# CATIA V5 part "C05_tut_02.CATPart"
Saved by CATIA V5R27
Part number: Part1
Bounding box of the stored display mesh (mm): x -20 to 5, y -42.139 to 42.139, z 0 to 101.99
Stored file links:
  E:\_Deepak\2017_Deepak\CATIA\Resources\Tutorial Files\Tutorials\c05_catia_v5_6r2016_tut\C05_tut_02.CATPart
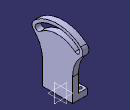
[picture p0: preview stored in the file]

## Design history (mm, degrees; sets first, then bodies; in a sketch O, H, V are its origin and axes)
Body1 (main body)
  Sketch1 on yz-plane, origin (0, 0, 0), H (0, 1, 0), V (0, 0, 1)
    point P1 (-25, 0)
    line L1 (-25, 0) -> (25, 0)
    point P2 (25, 0)
    line L2 (-25, 0) -> (-25, 38.3145)
    point P3 (-25, 38.3145)
    arc A1 centre (0, 42) radius 60 from (38.5673, 87.9627) to (-38.5673, 87.9627) ccw
    point P4 (0, 42)
    axis line L3 (0, 42) -> (-54.0665, 106.434)
    point P5 (-54.0665, 106.434)
    point P6 (54.0665, 106.434)
    point P7 (0, 42)
    construction line L4 (0, 42) -> (54.0665, 106.434)
    point P8 (-38.5673, 87.9627)
    point P9 (38.5673, 87.9627)
    arc A2 centre (-32.1394, 80.3022) radius 10 from (-38.5673, 87.9627) to (-39.2828, 73.3043) ccw
    point P10 (-32.1394, 80.3022)
    arc A3 centre (32.1394, 80.3022) radius 10 from (38.5673, 87.9627) to (39.2828, 73.3043) cw
    arc A4 centre (-75, 38.3145) radius 50 from (-25, 38.3145) to (-39.2828, 73.3043) ccw
    arc A5 centre (75, 38.3145) radius 50 from (25, 38.3145) to (39.2828, 73.3043) cw
    point P14 (25, 38.3145)
    point P15 (25, 0)
    line L5 (25, 0) -> (25, 38.3145)
    point P17 (25, 38.3145)
    length L1 = 50
    angle L4 L3 = 80
    radius A1 = 60
    radius A2 = 10
    radius A5 = 50
    distance P4 L1 = 42
    coincidence: P1 H, P4 V, L3 P8, L4 P9, P10 L3, L5 P17, P2 P15, P14 P17
    horizontal: L1 H
    symmetry: P2 P1 V, P5 P6 V, P4 P7 V, L3 L4 V, A2 A3 V, A4 A5 V, P3 P14 V, P1 P15 V, L2 L5 V
    vertical: L2 V
    tangency: A2 A1, A4 A2, A4 L2, A5 A3, L5 A5
  Pad1: profile Sketch1, direction (1, 0, 0), length 5, mirrored extent
  Sketch2 on start face of Pad1, origin (-5, 0, 0), H (0, -1, 0), V (0, 0, 1)
    construction arc A1 centre (0, 42) radius 50 from (32.1394, 80.3022) to (-32.1394, 80.3022) ccw
    point P1 (0, 42)
    arc A2 centre (32.1394, 80.3022) radius 5 from (35.3533, 84.1324) to (28.9254, 76.472) cw
    arc A3 centre (-32.1394, 80.3022) radius 5 from (-28.9254, 76.472) to (-35.3533, 84.1324) cw
    arc A4 centre (0, 42) radius 45 from (28.9254, 76.472) to (-28.9254, 76.472) ccw
    arc A5 centre (0, 42) radius 55 from (-35.3533, 84.1324) to (35.3533, 84.1324) cw
    construction line L1 (-32.1394, 80.3022) -> (0, 42)
    construction line L2 (0, 42) -> (32.1394, 80.3022)
    radius A3 = 5
    radius A1 = 50
    angle L2 L1 = 80
    angle L2 V = 40
    distance P1 H = 42
    coincidence: P1 V
    tangency: A4 A3, A3 A5, A5 A2, A2 A4
    concentricity: A4 P1, A5 P1
  Pocket1: profile Sketch2, direction (1, 0, 0), through (limit type 6)
  Sketch3 on start face of Pad1, origin (-5, 0, 0), H (0, 1, 0), V (0, 0, 1)
    line L1 (-25, 10) -> (25, 10)
    line L2 (25, 10) -> (25, 0)
    line L3 (25, 0) -> (-25, 0)
    line L4 (-25, 0) -> (-25, 10)
    point P3 (25, 0)
    reference projected line E1 (25, 0) -> (25, 38.3145) from edge [face of Pad1 from Sketch1.L5 | end face of Pad1]
    reference projected line E2 (-25, 38.3145) -> (-25, 0) from edge [face of Pad1 from Sketch1.L2 | end face of Pad1]
    length L2 = 10
    horizontal: L1 H, L3 H
    vertical: L2 V, L4 V
    coincidence: P3 H, L2 E1, L4 E2
  Pad2: profile Sketch3, direction (-1, 0, 0), length 15
  Sketch4 on face of Pad2 from Sketch3.L1, origin (0, 0, 10), H (1, 0, 0), V (0, 1, 0)
    circle A1 centre (-14, 19) radius 2.5
    point P1 (-14, 19)
    reference projected line E1 (-5, 25) -> (-20, 25) from edge [face of Pad2 | face of Pad2 from Sketch3.L1]
    reference projected line E2 (-20, 25) -> (-20, -25) from edge [end face of Pad2 | face of Pad2 from Sketch3.L1]
    circle A2 centre (-14, -19) radius 2.5
    radius A1 = 2.5
    distance E1 P1 = 6
    distance E2 P1 = 6
    symmetry: A1 A2 H
  Pocket2: profile Sketch4, direction (0, 0, -1), through (limit type 3)
  Sketch5 on start face of Pad1, origin (-5, 0, 0), H (0, -1, 0), V (0, 0, 1)
    circle A1 centre (0, 40.6656) radius 11
    point P1 (0, 40.6656)
    circle A2 centre (0, 40.6656) radius 4
    radius A1 = 11
    radius A2 = 4
    coincidence: P1 V
  Pad3: profile Sketch5, direction (-1, 0, 0), length 9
